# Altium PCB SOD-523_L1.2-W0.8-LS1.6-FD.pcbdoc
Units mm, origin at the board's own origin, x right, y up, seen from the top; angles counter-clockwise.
Board outline 14.65 x 13.61 mm, 2 copper layers (Top Layer, Bottom Layer), stack 0 mm thick; 1 components, 0 nets, 2 pads, 0 vias.
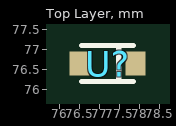
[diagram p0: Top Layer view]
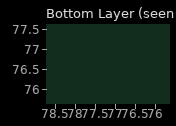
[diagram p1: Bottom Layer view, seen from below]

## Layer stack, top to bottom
Top Layer: signal copper (thickness not stored)
Bottom Layer: signal copper (thickness not stored)

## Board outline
84.5,69.85 69.85,69.85 69.85,83.46 84.5,83.46

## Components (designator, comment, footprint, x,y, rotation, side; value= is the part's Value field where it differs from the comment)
U? "" SOD-523_L1.2-W0.8-LS1.6-FD 77.2,76.66 r0 top

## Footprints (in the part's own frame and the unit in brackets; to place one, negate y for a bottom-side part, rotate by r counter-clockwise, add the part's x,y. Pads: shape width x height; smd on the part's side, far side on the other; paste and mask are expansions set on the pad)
SOD-523_L1.2-W0.8-LS1.6-FD [mm]
  rect 0.5x0.6 smd: 1(-0.7,0) 2(0.7,0)
  silkscreen extent -0.65,-0.45 0.65,0.45

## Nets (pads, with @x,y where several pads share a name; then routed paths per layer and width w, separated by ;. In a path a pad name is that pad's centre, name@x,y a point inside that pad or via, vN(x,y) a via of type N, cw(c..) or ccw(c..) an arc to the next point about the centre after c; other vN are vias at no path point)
pads on no net: U?.1 U?.2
